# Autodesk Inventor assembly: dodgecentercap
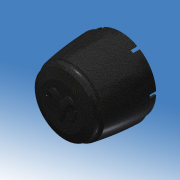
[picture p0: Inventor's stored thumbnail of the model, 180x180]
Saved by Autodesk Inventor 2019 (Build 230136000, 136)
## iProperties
Created: 2021-04
Part Number: dodgecentercap
Document SubType Name: Assembly
Designer: Caden
Author: Caden
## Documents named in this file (3)
- C:\Users\Caden\Documents\dodgecentercap.iam
- C:\Users\Caden\Documents\centercap.ipt
- C:\Users\Caden\Documents\derived dodge.ipt
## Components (2 placed, 2 different names)
1. centercap:1 — Mate:1
2. derived dodge:1 — Mate:1
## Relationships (1: Mate 1)
- Mate:1: centercap:1 ↔ derived dodge:1
